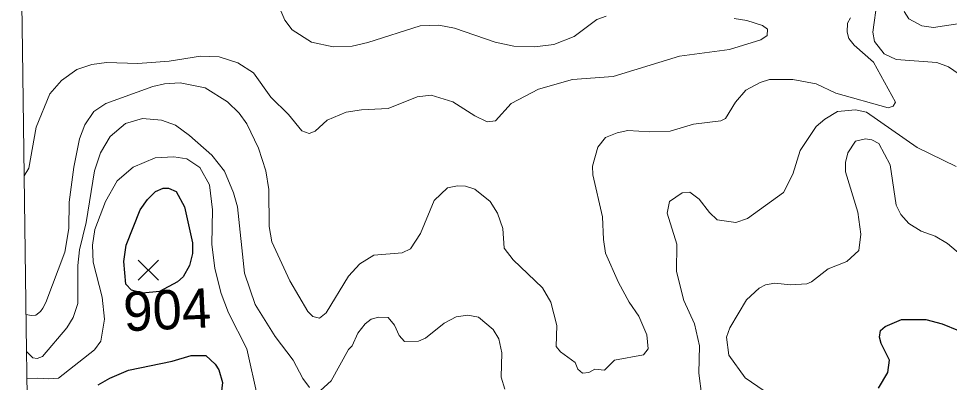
# Model space of a CAD drawing. Extents: x 265 to 291.4, y 7731.5 to 7759.6.
# Drawn here: x 265.242 to 267.136, y 7737.081 to 7737.823 of the extents above; entities that cross this region are included whole.
import ezdxf
from ezdxf.enums import TextEntityAlignment as Align

# ---------------------------------------------------------------- set-up
doc = ezdxf.new("R2010")
doc.units = 0
doc.header["$LTSCALE"] = 0.032
for name, color, linetype, lineweight in [('1', 7, 'Continuous', 25), ('2', 7, 'Continuous', 13), ('21', 7, 'Continuous', 25), ('61', 7, 'Continuous', 13), ('63', 7, 'Continuous', 25)]:
    doc.layers.add(name, color=color, linetype=linetype, lineweight=lineweight)

msp = doc.modelspace()

# ---------------------------------------------------------------- linework, layer by layer
at = {"layer": '1'}
msp.add_lwpolyline([(265.5281, 7737.267), (265.4936, 7737.2637), (265.4717, 7737.2696), (265.4597, 7737.2816), (265.4557, 7737.328), (265.4605, 7737.3615), (265.4891, 7737.433), (265.5042, 7737.4545), (265.5201, 7737.4704), (265.536, 7737.4776), (265.5464, 7737.4776), (265.5623, 7737.4704), (265.579, 7737.4394), (265.5957, 7737.3662), (265.5957, 7737.344), (265.5893, 7737.3201), (265.5766, 7737.297), (265.5647, 7737.2867)], close=True, dxfattribs=at)
for points in [[(266.9918, 7737.0695), (267.0109, 7737.1013), (267.0141, 7737.1268), (266.9973, 7737.161), (266.9942, 7737.1737), (266.9957, 7737.1872), (267.0053, 7737.1952), (267.0387, 7737.2095), (267.088, 7737.2095), (267.1215, 7737.2007), (267.1549, 7737.1872)], [(265.4032, 7737.0766), (265.4271, 7737.0902), (265.4653, 7737.1061), (265.5544, 7737.1244), (265.5925, 7737.1363), (265.6228, 7737.1363), (265.6418, 7737.1188), (265.649, 7737.1069), (265.6569, 7737.0814), (265.649, 7737.0178)]]:
    msp.add_lwpolyline(points, dxfattribs=at)
at = {"layer": '2'}
for points in [[(266.4373, 7737.8284), (266.4182, 7737.8212), (266.3721, 7737.787), (266.3307, 7737.7703), (266.2926, 7737.7656), (266.2496, 7737.7671), (266.2114, 7737.7751), (266.1287, 7737.8037), (266.0969, 7737.8101), (266.0587, 7737.8085), (265.9521, 7737.7743), (265.9203, 7737.7671), (265.8821, 7737.7656), (265.8375, 7737.7751), (265.7986, 7737.8006), (265.7834, 7737.8197), (265.7675, 7737.8578)], [(267.1692, 7737.7011), (267.1342, 7737.725), (267.1103, 7737.7337), (267.0276, 7737.7401), (267.0037, 7737.7512), (266.9838, 7737.7767), (266.9806, 7737.7958), (266.9894, 7737.8594)], [(265.2529, 7737.5025), (265.2624, 7737.5182), (265.2775, 7737.6017), (265.3054, 7737.6701), (265.3292, 7737.6971), (265.3603, 7737.7194), (265.3905, 7737.7298), (265.4207, 7737.7337), (265.4843, 7737.7313), (265.548, 7737.7361), (265.6116, 7737.7465), (265.6498, 7737.7449), (265.688, 7737.7329), (265.7198, 7737.7123), (265.7548, 7737.6629), (265.7906, 7737.6279), (265.8184, 7737.5945), (265.8328, 7737.5889), (265.8455, 7737.5937), (265.8694, 7737.616), (265.9083, 7737.6327), (265.9394, 7737.6375), (265.9935, 7737.6399), (266.0531, 7737.6637), (266.081, 7737.6669), (266.1255, 7737.6534), (266.1701, 7737.6247), (266.1955, 7737.6128), (266.2122, 7737.6144), (266.244, 7737.6502), (266.2997, 7737.6796), (266.3689, 7737.6987), (266.4517, 7737.7051), (266.5869, 7737.7465), (266.6887, 7737.76), (266.7524, 7737.7799), (266.7651, 7737.7886), (266.7659, 7737.8014), (266.7555, 7737.8093), (266.7237, 7737.8196), (266.6983, 7737.8236)], [(266.9347, 7737.8246), (266.9289, 7737.8141), (266.9281, 7737.7958), (266.9313, 7737.7823), (266.9425, 7737.7687), (266.9814, 7737.7345), (267.0268, 7737.6526), (267.022, 7737.6446), (267.0117, 7737.6414), (266.9051, 7737.6709), (266.8653, 7737.69), (266.8176, 7737.6987), (266.7699, 7737.6987), (266.7508, 7737.6932), (266.7221, 7737.6772), (266.7006, 7737.6526), (266.6807, 7737.6192), (266.6712, 7737.6144), (266.6155, 7737.608), (266.5678, 7737.5937)], [(267.0443, 7737.8379), (267.0538, 7737.8228), (267.0801, 7737.8085), (267.104, 7737.8053), (267.1978, 7737.8196), (267.2519, 7737.8324)], [(266.4095, 7737.5221), (266.4103, 7737.5046), (266.4302, 7737.4187), (266.4318, 7737.3726), (266.4365, 7737.3447), (266.4628, 7737.2851), (266.4843, 7737.2453), (266.5042, 7737.2167), (266.5201, 7737.1785), (266.5232, 7737.1499), (266.5137, 7737.1379), (266.4548, 7737.1268), (266.4341, 7737.1061), (266.4143, 7737.1085), (266.4023, 7737.1013), (266.3896, 7737.1005), (266.3801, 7737.1085), (266.3745, 7737.122), (266.3443, 7737.1435), (266.3355, 7737.1546), (266.3371, 7737.1976), (266.3252, 7737.2453), (266.3077, 7737.274), (266.248, 7737.3312), (266.2297, 7737.3551), (266.2273, 7737.3949), (266.2162, 7737.4267), (266.2011, 7737.4506), (266.1701, 7737.4752), (266.151, 7737.4816), (266.1351, 7737.4824), (266.1144, 7737.4784), (266.0873, 7737.4521), (266.0595, 7737.3853), (266.0396, 7737.3535), (266.0221, 7737.3455), (265.9648, 7737.3408), (265.9362, 7737.3233), (265.9131, 7737.2978), (265.8678, 7737.223), (265.8542, 7737.2127), (265.8407, 7737.2159), (265.8304, 7737.2262), (265.7938, 7737.2883), (265.7572, 7737.3678), (265.7516, 7737.3996), (265.7508, 7737.4744), (265.7445, 7737.5126), (265.7301, 7737.5587), (265.7063, 7737.6088), (265.6904, 7737.6303), (265.6665, 7737.6534), (265.6212, 7737.682), (265.5703, 7737.6924), (265.5384, 7737.69), (265.5146, 7737.6844), (265.4191, 7737.6502), (265.3945, 7737.6335), (265.3762, 7737.6065), (265.3658, 7737.5778), (265.3539, 7737.5206), (265.3443, 7737.449), (265.3435, 7737.3949), (265.3356, 7737.3471), (265.2967, 7737.2445), (265.291, 7737.2326), (265.2862, 7737.2258), (265.2765, 7737.2188), (265.2673, 7737.2176), (265.2567, 7737.2198)], [(266.8327, 7737.554), (266.8653, 7737.6033), (266.8828, 7737.6184), (266.9083, 7737.6335), (266.9449, 7737.6375), (266.9671, 7737.6327), (267.0705, 7737.5603)], [(265.2578, 7737.1447), (265.2706, 7737.1316), (265.2795, 7737.13), (265.2903, 7737.1339), (265.3396, 7737.1928), (265.3523, 7737.2135), (265.3618, 7737.2421), (265.3618, 7737.3201), (265.3658, 7737.3519), (265.3793, 7737.4076), (265.396, 7737.5126), (265.408, 7737.5492), (265.4279, 7737.5826), (265.4589, 7737.6096), (265.4939, 7737.6192), (265.5321, 7737.616), (265.5607, 7737.6057), (265.5894, 7737.585), (265.6347, 7737.5444), (265.6609, 7737.5118), (265.6792, 7737.4681), (265.6872, 7737.4394), (265.7015, 7737.3042), (265.723, 7737.2405), (265.7636, 7737.1753), (265.8001, 7737.1268), (265.82, 7737.0894), (265.8335, 7737.0711)], [(266.5678, 7737.5937), (266.5264, 7737.5921), (266.4819, 7737.5953), (266.4596, 7737.5905), (266.4365, 7737.581), (266.4206, 7737.5611), (266.4095, 7737.5221)], [(267.1588, 7737.3424), (267.1326, 7737.3646), (267.1071, 7737.3797), (267.0785, 7737.3901), (267.0538, 7737.4052), (267.0371, 7737.4235), (267.0276, 7737.4426), (267.0157, 7737.5253), (266.9926, 7737.5683), (266.9783, 7737.5762), (266.9655, 7737.5778), (266.9449, 7737.573), (266.9297, 7737.5492), (266.925, 7737.5301), (266.925, 7737.511), (266.9496, 7737.4283), (266.956, 7737.3837), (266.952, 7737.3503), (266.9274, 7737.328), (266.8892, 7737.3129), (266.8558, 7737.2867), (266.8462, 7737.2827), (266.8128, 7737.2803), (266.781, 7737.2835), (266.7619, 7737.2803), (266.7492, 7737.2739), (266.7229, 7737.2501), (266.6895, 7737.1928), (266.6823, 7737.1737), (266.6871, 7737.1371), (266.7205, 7737.091), (266.8001, 7737.0361)], [(267.0705, 7737.5603), (267.1501, 7737.5213)], [(265.7285, 7737.0496), (265.7063, 7737.1499), (265.6689, 7737.223), (265.6538, 7737.2628), (265.641, 7737.3137), (265.6347, 7737.363), (265.6363, 7737.433), (265.6299, 7737.484), (265.6108, 7737.5198), (265.5838, 7737.5372), (265.5575, 7737.5412), (265.5193, 7737.5396), (265.4748, 7737.5205), (265.4422, 7737.4927), (265.4183, 7737.4506), (265.3968, 7737.3933), (265.3921, 7737.3615), (265.3936, 7737.3265), (265.4119, 7737.2549), (265.4167, 7737.2103), (265.4088, 7737.1658), (265.396, 7737.1475), (265.3228, 7737.0904), (265.3026, 7737.0884), (265.2807, 7737.0904), (265.2585, 7737.0892)], [(266.6322, 7737.0528), (266.6259, 7737.1005), (266.6274, 7737.1562), (266.6171, 7737.2008), (266.5956, 7737.2485), (266.5805, 7737.3074), (266.5813, 7737.363), (266.5614, 7737.4267), (266.5662, 7737.4506), (266.5925, 7737.468), (266.6076, 7737.4696), (266.6267, 7737.4553), (266.6481, 7737.4275), (266.6632, 7737.4132), (266.7014, 7737.4076), (266.7253, 7737.4155), (266.7985, 7737.4688), (266.8176, 7737.5062), (266.8327, 7737.554)], [(265.8558, 7737.0647), (265.8781, 7737.0846), (265.9131, 7737.1483), (265.9203, 7737.1562), (265.9322, 7737.1817), (265.9473, 7737.2008), (265.9592, 7737.2103), (265.9744, 7737.2143), (265.9935, 7737.2135), (266.007, 7737.1984), (266.0165, 7737.1769), (266.0269, 7737.165), (266.0555, 7737.1658), (266.0698, 7737.1713), (266.108, 7737.2023), (266.1319, 7737.2151), (266.1557, 7737.2183), (266.178, 7737.2143), (266.2074, 7737.1896), (266.2194, 7737.1705), (266.2249, 7737.1419), (266.2241, 7737.0918), (266.2313, 7737.0679)]]:
    msp.add_lwpolyline(points, dxfattribs=at)
at = {"layer": '21'}
for p, q in [((265.4848, 7737.3308), (265.526, 7737.2896)), ((265.526, 7737.3308), (265.4848, 7737.2896))]:
    msp.add_line(p, q, dxfattribs=at)
at = {"layer": '63', "lineweight": 13}
msp.add_lwpolyline([(265.2416, 7738.3238), (265.2494, 7737.7588), (265.2571, 7737.1938), (265.2649, 7736.6289), (265.2726, 7736.0639), (265.2804, 7735.499), (265.2882, 7734.934), (265.2959, 7734.369), (265.3037, 7733.8041), (265.3115, 7733.2391), (265.3192, 7732.6741), (265.327, 7732.1092), (265.3348, 7731.5442)], dxfattribs=at)

# ---------------------------------------------------------------- texts
at = {"layer": '61'}
msp.add_text('904', height=0.08, rotation=2.683, dxfattribs=at).set_placement((265.5458, 7737.1897), align=Align.CENTER)

doc.saveas('drawing.dxf')
